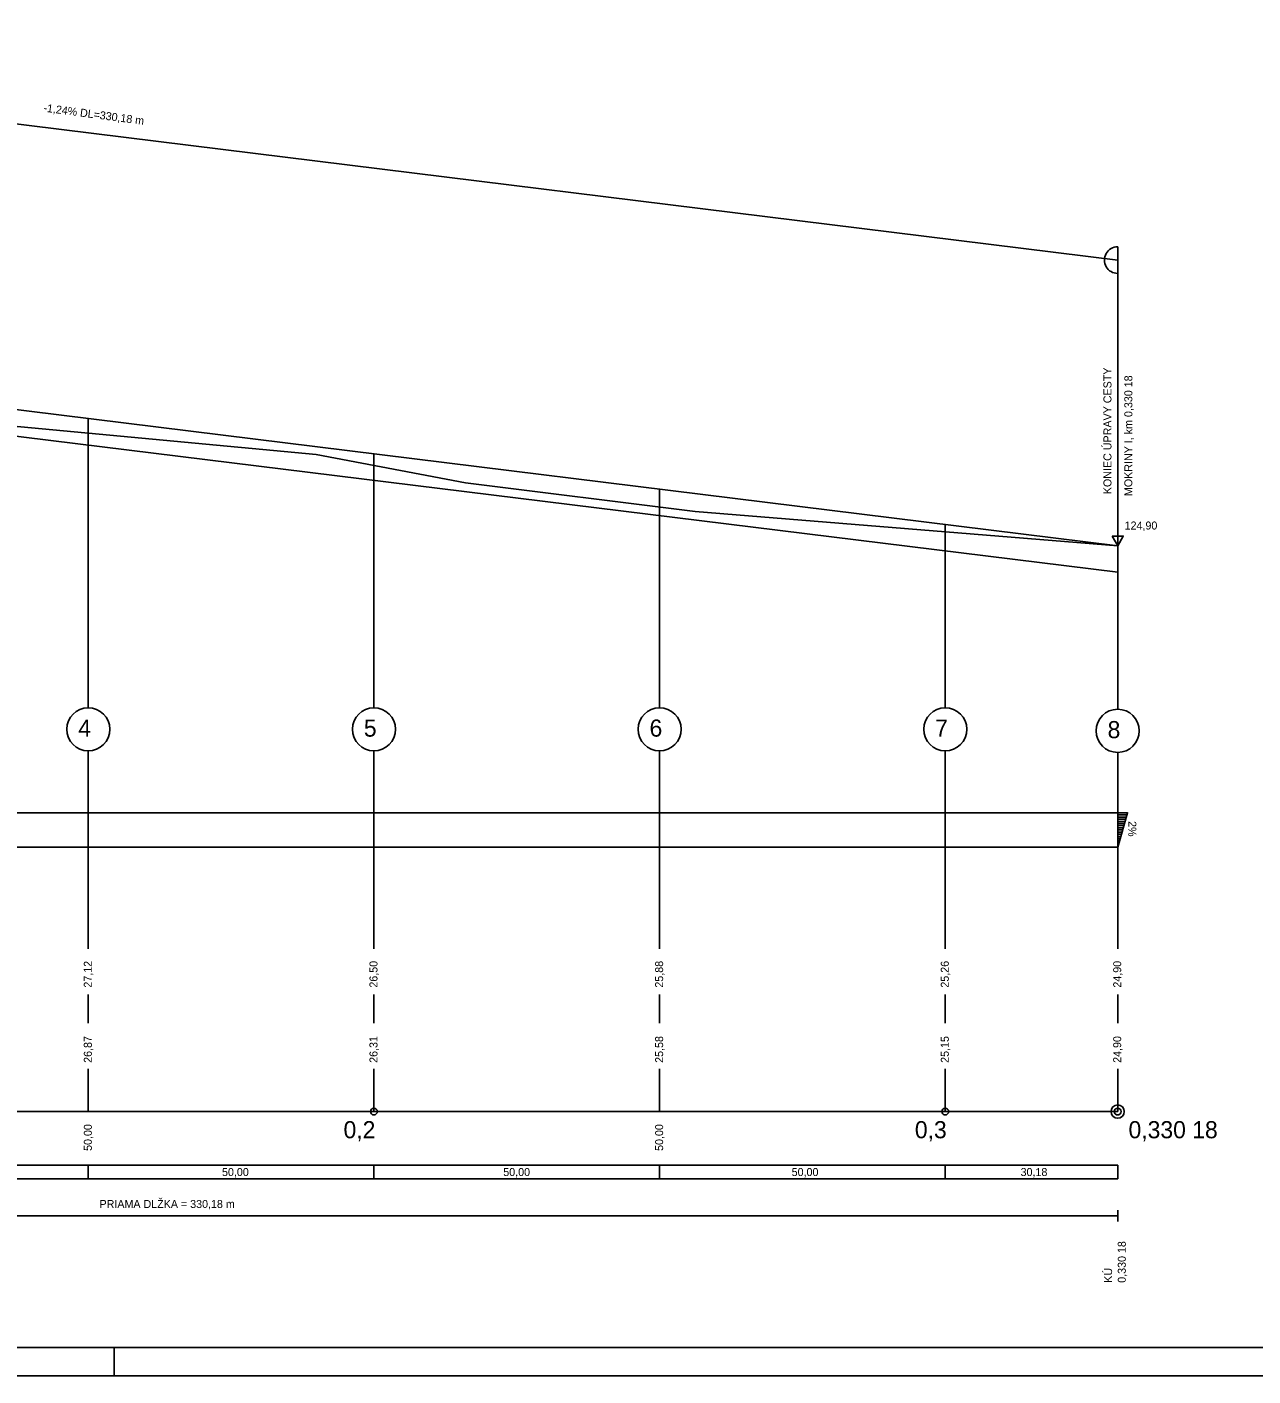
# Model space of a CAD drawing. Extents: x -499093 to -498458, y -1280289 to -1279879.
# Drawn here: x -498898.7 to -498684.1, y -1280289.4 to -1280053.3 of the extents above; entities that cross this region are included whole.
import ezdxf

# ---------------------------------------------------------------- set-up
doc = ezdxf.new("R2010")
doc.units = 0
for name, color, linetype in [('Vrstva 1', 7, 'Continuous'), ('Vrstva 11', 7, 'Continuous'), ('Vrstva 12', 7, 'Continuous'), ('Vrstva 13', 7, 'Continuous'), ('Vrstva 4', 7, 'Continuous'), ('Vrstva 8', 7, 'Continuous')]:
    doc.layers.add(name, color=color, linetype=linetype)

# ---------------------------------------------------------------- blocks, each defined once
blk = doc.blocks.new('SC97995')
at = {"layer": 'Vrstva 1'}
blk.add_line((0, 0), (0, 0), dxfattribs=at)

msp = doc.modelspace()

# ---------------------------------------------------------------- linework, layer by layer
at = {"layer": 'Vrstva 1'}
for p, q in [((-499088.41, -1280284.38), (-498468.41, -1280284.38)), ((-498883.41, -1280284.38), (-498883.41, -1280289.38)), ((-499093.41, -1280289.38), (-498463.41, -1280289.38))]:
    msp.add_line(p, q, dxfattribs=at)
at = {"layer": 'Vrstva 11'}
for p, q in [((-499037.95, -1280103.31), (-498707.77, -1280144.11)), ((-498706.02, -1280190.82), (-498707.77, -1280190.82)), ((-498706.13, -1280191.2), (-498707.77, -1280191.2)), ((-498706.24, -1280191.57), (-498707.77, -1280191.57)), ((-498706.35, -1280191.95), (-498707.77, -1280191.95)), ((-498706.46, -1280192.32), (-498707.77, -1280192.32)), ((-498706.57, -1280192.7), (-498707.77, -1280192.7)), ((-498706.68, -1280193.07), (-498707.77, -1280193.07)), ((-498706.78, -1280193.45), (-498707.77, -1280193.45)), ((-498706.89, -1280193.82), (-498707.77, -1280193.82)), ((-498707, -1280194.2), (-498707.77, -1280194.2)), ((-498707.11, -1280194.57), (-498707.77, -1280194.57)), ((-498707.22, -1280194.95), (-498707.77, -1280194.95)), ((-498707.33, -1280195.32), (-498707.77, -1280195.32)), ((-498707.44, -1280195.7), (-498707.77, -1280195.7)), ((-498707.55, -1280196.07), (-498707.77, -1280196.07)), ((-498707.66, -1280196.45), (-498707.77, -1280196.45)), ((-499036.78, -1280243.11), (-498707.77, -1280243.11)), ((-498887.95, -1280252.46), (-498887.95, -1280254.86)), ((-498837.95, -1280252.46), (-498837.95, -1280254.86)), ((-498787.95, -1280252.46), (-498787.95, -1280254.86)), ((-498737.95, -1280252.46), (-498737.95, -1280254.86)), ((-498707.77, -1280252.46), (-498707.77, -1280254.86))]:
    msp.add_line(p, q, dxfattribs=at)
msp.add_lwpolyline([(-498707.77, -1280190.81), (-498707.77, -1280196.81), (-498706.02, -1280190.81), (-498707.77, -1280190.81)], dxfattribs=at)
for centre in [(-498887.95, -1280176.21), (-498837.95, -1280176.21), (-498787.95, -1280176.21), (-498737.95, -1280176.21), (-498707.77, -1280176.48)]:
    msp.add_circle(centre, 3.77, dxfattribs=at)
at = {"layer": 'Vrstva 13'}
for p, q in [((-499037.95, -1280053.31), (-498707.77, -1280094.11)), ((-498707.77, -1280172.72), (-498707.77, -1280091.78)), ((-498887.95, -1280172.45), (-498887.95, -1280121.84)), ((-498901.65, -1280123.11), (-498848.05, -1280128.11)), ((-498848.05, -1280128.11), (-498821.9, -1280133.11)), ((-498837.95, -1280172.45), (-498837.95, -1280128.02)), ((-498821.9, -1280133.11), (-498781.7, -1280138.11)), ((-498787.95, -1280172.45), (-498787.95, -1280134.2)), ((-498781.7, -1280138.11), (-498707.77, -1280144.11)), ((-498737.95, -1280172.45), (-498737.95, -1280140.38)), ((-498887.95, -1280214.61), (-498887.95, -1280179.98)), ((-498837.95, -1280214.61), (-498837.95, -1280179.98)), ((-498787.95, -1280214.61), (-498787.95, -1280179.98)), ((-498737.95, -1280214.61), (-498737.95, -1280179.98)), ((-498707.77, -1280214.61), (-498707.77, -1280180.25)), ((-499037.95, -1280190.81), (-498707.77, -1280190.81)), ((-499037.95, -1280196.81), (-498707.77, -1280196.81)), ((-498887.95, -1280227.61), (-498887.95, -1280222.61)), ((-498837.95, -1280227.61), (-498837.95, -1280222.61)), ((-498787.95, -1280227.61), (-498787.95, -1280222.61)), ((-498737.95, -1280227.61), (-498737.95, -1280222.61)), ((-498707.77, -1280227.61), (-498707.77, -1280222.61)), ((-498887.95, -1280243.11), (-498887.95, -1280235.61)), ((-498837.95, -1280243.11), (-498837.95, -1280235.61)), ((-498787.95, -1280243.11), (-498787.95, -1280235.61)), ((-498737.95, -1280243.11), (-498737.95, -1280235.61)), ((-498707.77, -1280243.11), (-498707.77, -1280235.61))]:
    msp.add_line(p, q, dxfattribs=at)
msp.add_lwpolyline([(-498708.76, -1280142.39), (-498707.77, -1280144.11), (-498706.78, -1280142.39), (-498708.76, -1280142.39)], dxfattribs=at)
for centre, radius in [((-498837.95, -1280243.11), 0.592), ((-498737.95, -1280243.11), 0.592), ((-498707.77, -1280243.11), 1.16), ((-498707.77, -1280243.11), 0.592)]:
    msp.add_circle(centre, radius, dxfattribs=at)
msp.add_arc((-498707.77, -1280094.11), 2.33, 89.9981, 270.0019, dxfattribs=at)
at = {"layer": 'Vrstva 8'}
for p, q in [((-499037.95, -1280107.94), (-498707.77, -1280148.74)), ((-499036.78, -1280243.11), (-498707.77, -1280243.11)), ((-499037.95, -1280252.46), (-498707.77, -1280252.46)), ((-499037.95, -1280254.86), (-498707.77, -1280254.86)), ((-499037.95, -1280261.36), (-498707.77, -1280261.36)), ((-498707.77, -1280262.36), (-498707.77, -1280260.36))]:
    msp.add_line(p, q, dxfattribs=at)

# ---------------------------------------------------------------- block references
at = {"layer": 'Vrstva 11'}
msp.add_blockref('SC97995', (-498707.77, -1280144.11), dxfattribs=at)

# ---------------------------------------------------------------- texts
at = {"layer": 'Vrstva 12'}
for s, rotation, p in [('KONIEC ÚPRAVY CESTY', 90, (-498708.86, -1280135.07)), ('MOKRINY I, km 0,330 18', 90, (-498705.2, -1280135.4)), ('2%', 270, (-498705.9, -1280192.28)), ('27,12', 90, (-498887.33, -1280221.42)), ('26,50', 90, (-498837.33, -1280221.42)), ('25,88', 90, (-498787.33, -1280221.42)), ('25,26', 90, (-498737.33, -1280221.42)), ('24,90', 90, (-498707.15, -1280221.42)), ('26,87', 90, (-498887.33, -1280234.58)), ('26,31', 90, (-498837.33, -1280234.58)), ('25,58', 90, (-498787.33, -1280234.58)), ('25,15', 90, (-498737.33, -1280234.58)), ('24,90', 90, (-498707.15, -1280234.58)), ('50,00', 90, (-498887.33, -1280249.99)), ('50,00', 90, (-498787.33, -1280249.99)), ('0,330 18', 90, (-498706.35, -1280273.07)), ('KÚ', 90, (-498708.75, -1280273.07))]:
    msp.add_text(s, height=1.4, rotation=rotation, dxfattribs=at).set_placement(p)
for s, height, p in [('124,90', 1.4, (-498706.55, -1280141.25)), ('4', 3, (-498889.71, -1280177.5)), ('5', 3, (-498839.71, -1280177.5)), ('6', 3, (-498789.71, -1280177.5)), ('7', 3, (-498739.71, -1280177.5)), ('8', 3, (-498709.53, -1280177.77)), ('0,2', 3, (-498843.27, -1280247.78)), ('0,3', 3, (-498743.27, -1280247.78)), ('0,330 18', 3, (-498705.87, -1280247.78)), ('50,00', 1.4, (-498864.54, -1280254.39)), ('50,00', 1.4, (-498815.31, -1280254.39)), ('50,00', 1.4, (-498764.83, -1280254.39)), ('30,18', 1.4, (-498724.76, -1280254.39)), ('PRIAMA DLŽKA = 330,18 m', 1.4, (-498885.98, -1280259.98))]:
    msp.add_text(s, height=height, dxfattribs=at).set_placement(p)
at = {"layer": 'Vrstva 4'}
msp.add_text('-1,24% DL=330,18 m', height=1.4, rotation=352.4777, dxfattribs=at).set_placement((-498895.86, -1280068.11))

doc.saveas('drawing.dxf')
